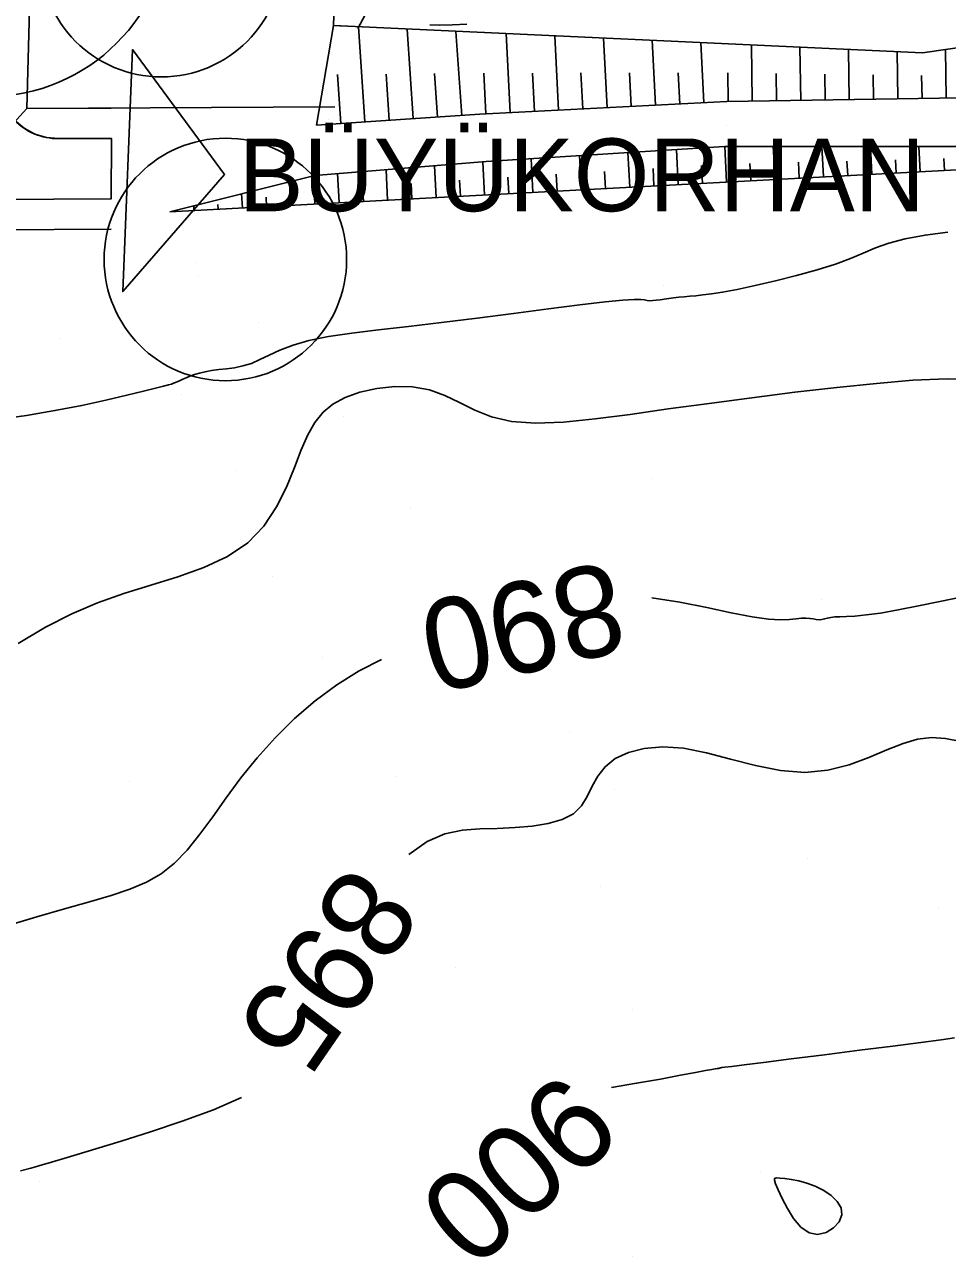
# Model space of a CAD drawing. Extents: x 400243 to 403697, y 4403637 to 4408083.
# Drawn here: x 402707.4 to 402783.5, y 4405990.3 to 4406092.2 of the extents above; entities that cross this region are included whole.
import ezdxf

# ---------------------------------------------------------------- set-up
doc = ezdxf.new("R2010")
doc.units = 0
for name, color, linetype in [('ADAKENARI', 7, 'Continuous'), ('HH_IC', 7, 'Continuous'), ('KALDIRIM', 7, 'Continuous'), ('PL_YAZI', 7, 'Continuous'), ('PL_YOL', 7, 'Continuous'), ('SM_DAIRE', 7, 'Continuous'), ('SNR_MULKIYET', 7, 'Continuous'), ('SNR_ONAMA', 7, 'Continuous')]:
    doc.layers.add(name, color=color, linetype=linetype)

msp = doc.modelspace()

# ---------------------------------------------------------------- linework, layer by layer
at = {"layer": 'ADAKENARI'}
for p, q in [((402709, 4406140.88), (402707.56, 4406085.27)), ((402707.56, 4406085.27), (402714.51, 4406085.31)), ((402698.29, 4406075.22), (402714.51, 4406075.31))]:
    msp.add_line(p, q, dxfattribs=at)
at = {"layer": 'HH_IC'}
for p, q in [((402752.53, 4406124.67), (402734.84, 4406091.88)), ((402732.84, 4406092.11), (402733.27, 4406104.64)), ((402731.45, 4406083.9), (402732.84, 4406092.11)), ((402732.84, 4406092.11), (402732.84, 4406092.11)), ((402781.43, 4406089.87), (402732.84, 4406092.11)), ((402733.88, 4406092.07), (402732.84, 4406092.11)), ((402735.44, 4406084.17), (402734.91, 4406092.01)), ((402739.43, 4406084.44), (402738.93, 4406091.83)), ((402743.42, 4406084.71), (402742.95, 4406091.64)), ((402747.42, 4406084.94), (402747.09, 4406091.45)), ((402751.41, 4406085.14), (402751.1, 4406091.27)), ((402755.41, 4406085.34), (402755.12, 4406091.08)), ((402759.4, 4406085.54), (402759.13, 4406090.9)), ((402763.4, 4406085.74), (402763.15, 4406090.71)), ((402767.39, 4406085.87), (402767.32, 4406090.52)), ((402790.08, 4406091.13), (402781.43, 4406089.87)), ((402771.39, 4406085.94), (402771.32, 4406090.34)), ((402775.39, 4406086), (402775.33, 4406090.15)), ((402779.39, 4406086.06), (402779.33, 4406089.97)), ((402781.43, 4406089.87), (402781.43, 4406089.87)), ((402783.39, 4406086.13), (402783.33, 4406090.15)), ((402733.17, 4406088.07), (402733.45, 4406084.03)), ((402737.18, 4406088.11), (402737.44, 4406084.3)), ((402741.19, 4406088.15), (402741.43, 4406084.57)), ((402745.25, 4406088.19), (402745.42, 4406084.84)), ((402749.26, 4406088.2), (402749.42, 4406085.04)), ((402753.26, 4406088.21), (402753.41, 4406085.24)), ((402757.27, 4406088.22), (402757.41, 4406085.44)), ((402761.27, 4406088.22), (402761.4, 4406085.64)), ((402765.36, 4406088.23), (402765.4, 4406085.84)), ((402769.36, 4406088.17), (402769.39, 4406085.91)), ((402773.36, 4406088.11), (402773.39, 4406085.97)), ((402777.36, 4406088.05), (402777.39, 4406086.03)), ((402781.36, 4406087.99), (402781.39, 4406086.1)), ((402717.83, 4406087.38), (402717.83, 4406087.38)), ((402779.09, 4406086.58), (402779.09, 4406086.58)), ((402744.92, 4406084.81), (402765.3, 4406085.84)), ((402744.92, 4406084.81), (402765.3, 4406085.84)), ((402765.3, 4406085.84), (402784.58, 4406086.15)), ((402765.3, 4406085.84), (402784.58, 4406086.15)), ((402765.3, 4406085.84), (402765.3, 4406085.84)), ((402731.45, 4406083.9), (402744.92, 4406084.81)), ((402731.45, 4406083.9), (402744.92, 4406084.81)), ((402744.92, 4406084.81), (402744.92, 4406084.81)), ((402746.95, 4406085.21), (402746.95, 4406085.21)), ((402731.45, 4406083.9), (402731.45, 4406083.9)), ((402732.44, 4406084.34), (402732.44, 4406084.34)), ((402765.24, 4406083.91), (402765.24, 4406083.91)), ((402745.38, 4406082.87), (402745.38, 4406082.87)), ((402731.19, 4406082.2), (402731.19, 4406082.2)), ((402765.11, 4406082.15), (402745.44, 4406080.89)), ((402765.11, 4406082.15), (402745.44, 4406080.89)), ((402765.11, 4406082.15), (402745.44, 4406080.89)), ((402753.29, 4406078.57), (402753.14, 4406081.38)), ((402757.29, 4406078.78), (402757.13, 4406081.64)), ((402761.28, 4406078.99), (402761.13, 4406081.89)), ((402784.29, 4406082.15), (402765.11, 4406082.15)), ((402784.29, 4406082.15), (402765.11, 4406082.15)), ((402784.29, 4406082.15), (402765.11, 4406082.15)), ((402765.11, 4406082.15), (402765.11, 4406082.15)), ((402765.27, 4406079.21), (402765.12, 4406082.15)), ((402769.27, 4406079.42), (402769.12, 4406082.15)), ((402773.26, 4406079.63), (402773.13, 4406082.15)), ((402777.26, 4406079.84), (402777.13, 4406082.15)), ((402781.25, 4406080.06), (402781.14, 4406082.15)), ((402719.34, 4406076.76), (402789.63, 4406080.5)), ((402719.34, 4406076.76), (402789.63, 4406080.5)), ((402745.44, 4406080.89), (402731.32, 4406079.75)), ((402745.44, 4406080.89), (402731.32, 4406079.75)), ((402745.44, 4406080.89), (402731.32, 4406079.75)), ((402741.31, 4406077.93), (402741.17, 4406080.54)), ((402745.3, 4406078.14), (402745.16, 4406080.86)), ((402745.44, 4406080.89), (402745.44, 4406080.89)), ((402749.3, 4406078.36), (402749.15, 4406081.12)), ((402759.21, 4406080.33), (402759.28, 4406078.89)), ((402763.2, 4406080.56), (402763.28, 4406079.1)), ((402767.2, 4406080.73), (402767.27, 4406079.31)), ((402771.2, 4406080.84), (402771.27, 4406079.53)), ((402775.2, 4406080.94), (402775.26, 4406079.74)), ((402779.2, 4406081.05), (402779.25, 4406079.95)), ((402783.2, 4406081.15), (402783.25, 4406080.16)), ((402731.32, 4406079.75), (402719.34, 4406076.76)), ((402731.32, 4406079.75), (402719.34, 4406076.76)), ((402731.32, 4406079.75), (402731.32, 4406079.75)), ((402733.32, 4406077.51), (402733.19, 4406079.9)), ((402737.31, 4406077.72), (402737.18, 4406080.22)), ((402743.23, 4406079.37), (402743.31, 4406078.04)), ((402747.23, 4406079.62), (402747.3, 4406078.25)), ((402751.22, 4406079.86), (402751.29, 4406078.46)), ((402755.21, 4406080.09), (402755.29, 4406078.68)), ((402725.33, 4406077.08), (402725.27, 4406078.24)), ((402729.32, 4406077.3), (402729.22, 4406079.23)), ((402731.26, 4406078.56), (402731.32, 4406077.4)), ((402735.25, 4406078.84), (402735.32, 4406077.61)), ((402739.24, 4406079.1), (402739.31, 4406077.83)), ((402721.34, 4406076.87), (402721.32, 4406077.26)), ((402723.31, 4406077.36), (402723.33, 4406076.98)), ((402727.29, 4406077.96), (402727.33, 4406077.19)), ((402719.34, 4406076.76), (402719.34, 4406076.76)), ((402719.34, 4406076.76), (402719.34, 4406076.76)), ((402721.46, 4406072.53), (402721.46, 4406072.53)), ((402721.7, 4406071.53), (402721.7, 4406071.53)), ((402760.09, 4406070.66), (402760.09, 4406070.66)), ((402715.32, 4406068.16), (402715.32, 4406068.16)), ((402726.68, 4406067.65), (402726.68, 4406067.65)), ((402710.33, 4406066.3), (402710.33, 4406066.3)), ((402731.08, 4406065.71), (402731.08, 4406065.71)), ((402720.31, 4406061.71), (402720.31, 4406061.71)), ((402733.64, 4406059.89), (402733.64, 4406059.89)), ((402724.82, 4406055.4), (402724.82, 4406055.4)), ((402759.1, 4406054.74), (402759.1, 4406054.74)), ((402739.2, 4406052.24), (402739.2, 4406052.24)), ((402727.85, 4406046.66), (402727.85, 4406046.66)), ((402773.06, 4406044.73), (402773.06, 4406044.73)), ((402745.46, 4406042.79), (402745.46, 4406042.79)), ((402731.94, 4406039.95), (402731.94, 4406039.95)), ((402752.33, 4406033.76), (402752.33, 4406033.76)), ((402716.05, 4406029.78), (402716.05, 4406029.78)), ((402738.01, 4406030.18), (402738.01, 4406030.18)), ((402756.02, 4406029.13), (402756.02, 4406029.13)), ((402771.95, 4406023.44), (402771.95, 4406023.44)), ((402754.9, 4406021.08), (402754.9, 4406021.08)), ((402782.76, 4406019.29), (402782.76, 4406019.29)), ((402742.88, 4406014.4), (402742.88, 4406014.4)), ((402725.28, 4406011.57), (402725.28, 4406011.57)), ((402757.51, 4406010.94), (402757.51, 4406010.94)), ((402764.71, 4406006.17), (402764.71, 4406006.17)), ((402749.67, 4406002.91), (402749.67, 4406002.91)), ((402708.63, 4405996.75), (402708.63, 4405996.75)), ((402768.05, 4405997.55), (402768.05, 4405997.55)), ((402769.24, 4405997.01), (402769.24, 4405997.01)), ((402757.51, 4405990.59), (402757.51, 4405990.59))]:
    msp.add_line(p, q, dxfattribs=at)
for points in [[(402743.84, 4406092.24), (402742.67, 4406092.18), (402741.59, 4406092.16), (402740.8, 4406092.18)], [(402783.52, 4406075.08), (402781.64, 4406074.83), (402779.99, 4406074.52), (402778.66, 4406074.17), (402777.56, 4406073.78), (402776.54, 4406073.35), (402775.49, 4406072.91), (402774.25, 4406072.44), (402772.74, 4406071.96), (402771.05, 4406071.49), (402769.3, 4406071.05), (402767.62, 4406070.66), (402766.13, 4406070.34), (402764.94, 4406070.12), (402764.02, 4406069.98), (402763.3, 4406069.89), (402762.72, 4406069.83), (402762.23, 4406069.79), (402761.76, 4406069.75), (402761.32, 4406069.7), (402760.9, 4406069.65), (402760.5, 4406069.6), (402760.13, 4406069.55), (402759.78, 4406069.5), (402759.47, 4406069.46), (402759.18, 4406069.43), (402758.93, 4406069.42), (402758.72, 4406069.44), (402758.51, 4406069.48), (402758.21, 4406069.52), (402757.66, 4406069.53), (402756.72, 4406069.47), (402755.25, 4406069.33), (402753.16, 4406069.09), (402750.58, 4406068.75), (402747.7, 4406068.37), (402744.69, 4406067.98), (402741.75, 4406067.61), (402739.02, 4406067.29), (402736.55, 4406067.01), (402734.35, 4406066.74), (402732.44, 4406066.46), (402730.82, 4406066.13), (402729.51, 4406065.75), (402728.43, 4406065.34), (402727.55, 4406064.93), (402726.78, 4406064.56), (402726.08, 4406064.25), (402725.38, 4406064.04), (402724.68, 4406063.89), (402724.01, 4406063.8), (402723.38, 4406063.73), (402722.79, 4406063.66), (402722.26, 4406063.56), (402721.79, 4406063.44), (402721.37, 4406063.32), (402721.01, 4406063.18), (402720.69, 4406063.06), (402720.43, 4406062.94), (402720.2, 4406062.84), (402720, 4406062.75), (402719.82, 4406062.68), (402719.66, 4406062.61), (402719.49, 4406062.54), (402719.23, 4406062.47), (402718.82, 4406062.36), (402718.16, 4406062.19), (402717.17, 4406061.95), (402715.8, 4406061.62), (402714.08, 4406061.22), (402712.08, 4406060.78), (402709.87, 4406060.35), (402707.52, 4406059.96), (402705.07, 4406059.62)], [(402786.22, 4406062.93), (402783.47, 4406062.98), (402780.64, 4406062.85), (402777.63, 4406062.6), (402774.36, 4406062.26), (402770.9, 4406061.86), (402767.35, 4406061.41), (402763.84, 4406060.95), (402760.46, 4406060.49), (402757.31, 4406060.04), (402754.42, 4406059.67), (402751.81, 4406059.41), (402749.51, 4406059.32), (402747.54, 4406059.46), (402745.89, 4406059.84), (402744.5, 4406060.4), (402743.24, 4406061.02), (402742.03, 4406061.61), (402740.77, 4406062.07), (402739.37, 4406062.3), (402737.9, 4406062.33), (402736.42, 4406062.17), (402735.03, 4406061.86), (402733.81, 4406061.43), (402732.8, 4406060.88), (402731.99, 4406060.21), (402731.32, 4406059.38), (402730.73, 4406058.36), (402730.18, 4406057.12), (402729.62, 4406055.65), (402728.96, 4406054.04), (402728.15, 4406052.4), (402727.11, 4406050.83), (402725.77, 4406049.44), (402724.1, 4406048.31), (402722.14, 4406047.4), (402720.01, 4406046.64), (402717.78, 4406045.95), (402715.55, 4406045.26), (402713.39, 4406044.49), (402711.26, 4406043.59), (402709.1, 4406042.49), (402706.84, 4406041.14)], [(402759.1, 4406044.91), (402761.41, 4406044.55), (402763.63, 4406044.11), (402765.65, 4406043.68), (402767.38, 4406043.34), (402768.72, 4406043.15), (402769.73, 4406043.1), (402770.47, 4406043.12), (402771.02, 4406043.18), (402771.45, 4406043.23), (402771.82, 4406043.24), (402772.14, 4406043.21), (402772.42, 4406043.16), (402772.67, 4406043.12), (402772.9, 4406043.1), (402773.12, 4406043.12), (402773.35, 4406043.17), (402773.59, 4406043.23), (402773.87, 4406043.29), (402774.21, 4406043.34), (402774.62, 4406043.35), (402775.15, 4406043.36), (402775.86, 4406043.4), (402776.78, 4406043.49), (402777.96, 4406043.65), (402779.43, 4406043.92), (402781.11, 4406044.25), (402782.86, 4406044.61), (402784.59, 4406044.95)], [(402705.9, 4406017.86), (402708.37, 4406018.6), (402710.65, 4406019.25), (402712.71, 4406019.83), (402714.5, 4406020.36), (402716.06, 4406020.87), (402717.42, 4406021.45), (402718.63, 4406022.14), (402719.74, 4406023.01), (402720.79, 4406024.1), (402721.83, 4406025.4), (402722.88, 4406026.85), (402723.99, 4406028.42), (402725.21, 4406030.05), (402726.56, 4406031.71), (402728.04, 4406033.36), (402729.63, 4406034.94), (402731.33, 4406036.41), (402733.12, 4406037.74), (402734.96, 4406038.87), (402736.81, 4406039.83)], [(402739.05, 4406023.74), (402740.56, 4406024.81), (402742.03, 4406025.44), (402743.48, 4406025.75), (402744.92, 4406025.86), (402746.36, 4406025.89), (402747.82, 4406025.95), (402749.24, 4406026.07), (402750.55, 4406026.28), (402751.7, 4406026.62), (402752.63, 4406027.1), (402753.29, 4406027.76), (402753.78, 4406028.53), (402754.19, 4406029.36), (402754.64, 4406030.19), (402755.25, 4406030.97), (402756.09, 4406031.64), (402757.17, 4406032.16), (402758.48, 4406032.49), (402760, 4406032.62), (402761.71, 4406032.5), (402763.6, 4406032.12), (402765.6, 4406031.6), (402767.66, 4406031.07), (402769.72, 4406030.66), (402771.72, 4406030.5), (402773.61, 4406030.69), (402775.37, 4406031.14), (402777, 4406031.74), (402778.49, 4406032.37), (402779.83, 4406032.9), (402781.03, 4406033.24), (402782.16, 4406033.37), (402783.32, 4406033.3), (402784.59, 4406033.05)], [(402784.07, 4406008.6), (402782.96, 4406008.45), (402781.3, 4406008.23), (402778.98, 4406007.93), (402776.23, 4406007.58), (402773.34, 4406007.21), (402770.61, 4406006.87), (402768.32, 4406006.58), (402766.71, 4406006.38), (402765.69, 4406006.25), (402765.13, 4406006.18), (402764.88, 4406006.15), (402764.8, 4406006.13), (402764.75, 4406006.12), (402764.71, 4406006.11), (402764.66, 4406006.1), (402764.59, 4406006.09), (402764.49, 4406006.07), (402764.33, 4406006.04), (402764.04, 4406005.99), (402763.52, 4406005.9), (402762.7, 4406005.74), (402761.47, 4406005.52), (402759.81, 4406005.21), (402757.85, 4406004.86), (402755.79, 4406004.51)], [(402707.03, 4405997.63), (402707.87, 4405997.86), (402708.45, 4405998.02), (402708.89, 4405998.15), (402709.32, 4405998.27), (402709.85, 4405998.43), (402710.61, 4405998.66), (402711.7, 4405998.98), (402713.25, 4405999.45), (402715.32, 4406000.07), (402717.76, 4406000.84), (402720.37, 4406001.72), (402722.94, 4406002.68), (402725.27, 4406003.69)], [(402772.07, 4405992.52), (402772.78, 4405992.39), (402773.48, 4405992.55), (402774.1, 4405992.93), (402774.55, 4405993.44), (402774.77, 4405994.01), (402774.71, 4405994.58), (402774.4, 4405995.11), (402773.9, 4405995.6), (402773.28, 4405996.02), (402772.59, 4405996.36), (402771.9, 4405996.62), (402771.23, 4405996.8), (402770.61, 4405996.92), (402770.08, 4405996.99), (402769.66, 4405997.03), (402769.38, 4405997.05), (402769.23, 4405997.01), (402769.21, 4405996.86), (402769.31, 4405996.56), (402769.53, 4405996.07), (402769.86, 4405995.36), (402770.29, 4405994.52), (402770.8, 4405993.69), (402771.4, 4405992.98), (402772.07, 4405992.52)]]:
    msp.add_lwpolyline(points, dxfattribs=at)
at = {"layer": 'KALDIRIM'}
for p, q in [((402710.15, 4406082.79), (402714.53, 4406082.81)), ((402705.02, 4406077.76), (402714.5, 4406077.81))]:
    msp.add_line(p, q, dxfattribs=at)
msp.add_arc((402710.12, 4406087.79), 5, 178.5191, 270.3201, dxfattribs=at)
at = {"layer": 'PL_YAZI'}
msp.add_lwpolyline([(402723.85, 4406079.83), (402716.26, 4406090.14), (402715.46, 4406070.17)], close=True, dxfattribs=at)
at = {"layer": 'PL_YOL'}
msp.add_line((402714.53, 4406082.81), (402714.5, 4406077.81), dxfattribs=at)
msp.add_lwpolyline([(402710.15, 4406082.79), (402709.16, 4406082.88), (402708.2, 4406083.17), (402707.32, 4406083.65), (402706.55, 4406084.29), (402705.93, 4406085.07), (402705.47, 4406085.96), (402705.36, 4406086.34), (402703.74, 4406086.28), (402701.35, 4406086.57), (402700.1, 4406086.93), (402699.99, 4406082.89), (402700.07, 4406081.89), (402700.34, 4406080.93), (402700.8, 4406080.04), (402701.42, 4406079.26), (402702.19, 4406078.62), (402703.07, 4406078.14), (402704.02, 4406077.85), (402705.02, 4406077.76), (402714.5, 4406077.81), (402714.53, 4406082.81)], close=True, dxfattribs=at)
at = {"layer": 'SM_DAIRE'}
msp.add_circle((402704.35, 4406101.26), 15, dxfattribs=at)
at = {"layer": 'SNR_MULKIYET'}
for p, q in [((402707.56, 4406085.27), (402709, 4406140.88)), ((402707.56, 4406085.27), (402732.95, 4406085.42)), ((402609.95, 4405979.43), (402707.56, 4406085.27))]:
    msp.add_line(p, q, dxfattribs=at)
at = {"layer": 'SNR_ONAMA'}
for centre in [(402718.65, 4406097.88), (402723.93, 4406072.82)]:
    msp.add_circle(centre, 10, dxfattribs=at)

# ---------------------------------------------------------------- texts
at = {"layer": 'HH_IC'}
for s, rotation, p in [('890', 192.8593, (402755.8, 4406048.01)), ('895', 235.5039, (402734.11, 4406023.18)), ('900', 221.5701, (402751.9, 4406006.07))]:
    msp.add_text(s, height=7.5, rotation=rotation, dxfattribs=at).set_placement(p)
at = {"layer": 'PL_YAZI'}
msp.add_text('BÜYÜKORHAN', height=6, rotation=0, dxfattribs=at).set_placement((402725.02, 4406076.8))

doc.saveas('drawing.dxf')
